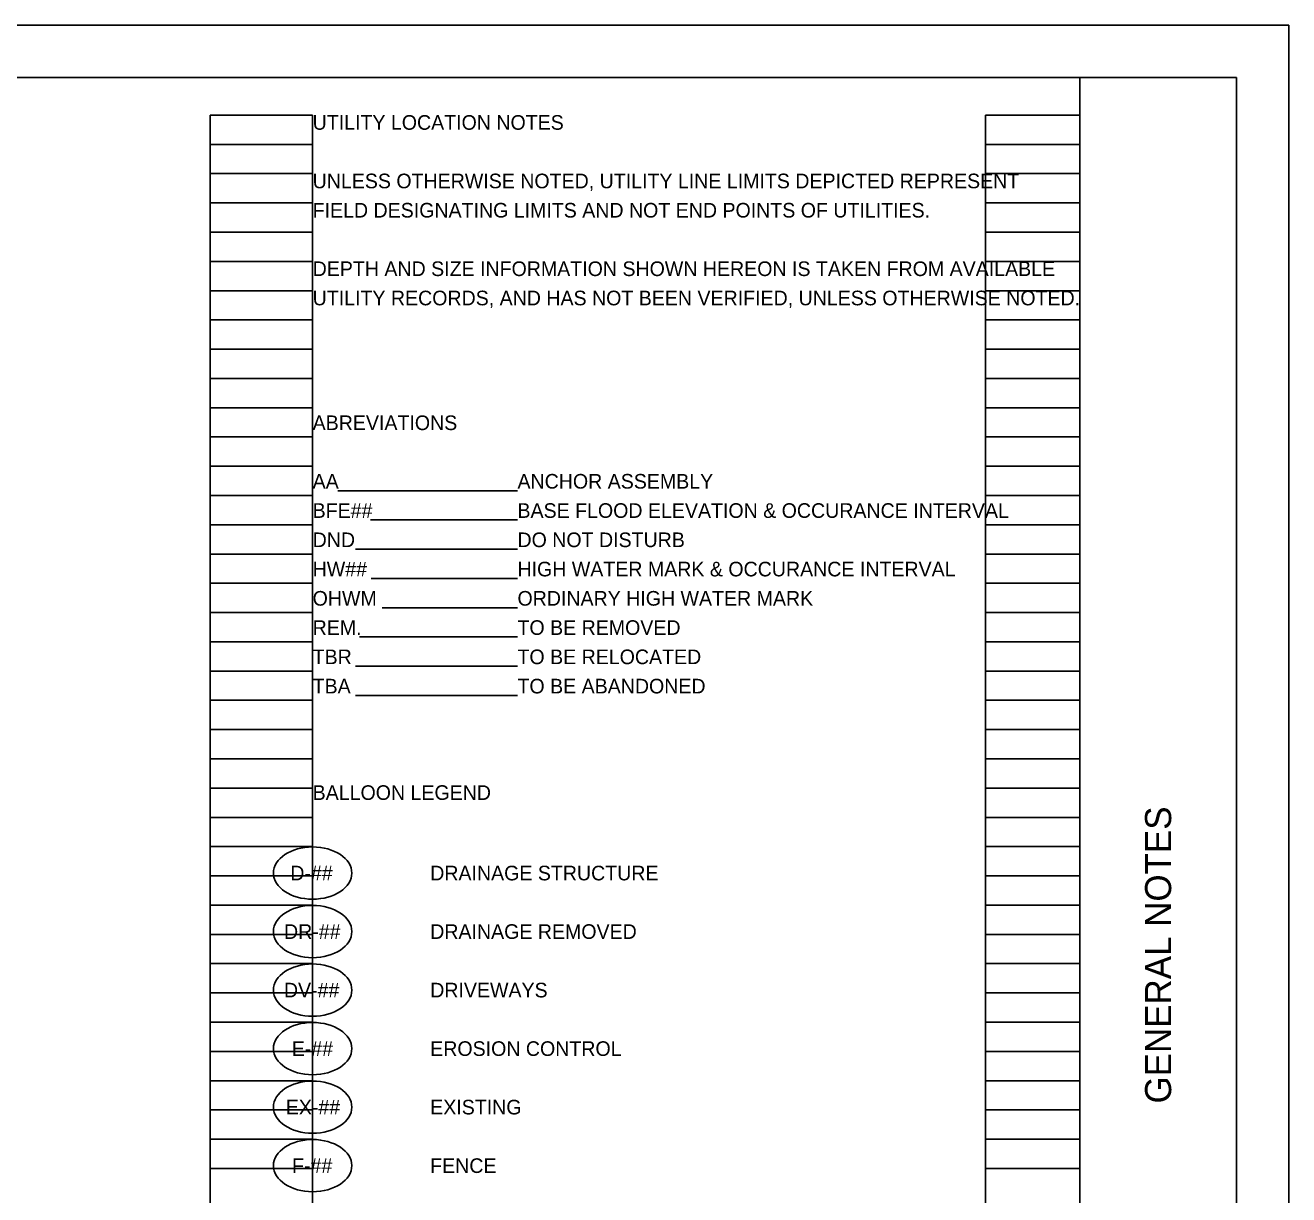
# Model space of a CAD drawing. Extents: x -8.3 to 34, y 0 to 22.
# Drawn here: x 21.91 to 34, y 10.81 to 22 of the extents above; entities that cross this region are included whole.
import ezdxf

# ---------------------------------------------------------------- set-up
doc = ezdxf.new("R2010")
doc.units = 0
for name, color, linetype in [('SH_Border', 7, 'Continuous'), ('SH_Cut_Line', 7, 'Continuous'), ('SH_Data', 7, 'Continuous'), ('SH_Text', 7, 'Continuous')]:
    doc.layers.add(name, color=color, linetype=linetype)

msp = doc.modelspace()

# ---------------------------------------------------------------- linework, layer by layer
at = {"layer": 'SH_Border'}
msp.add_line((32, 0.5), (32, 21.5), dxfattribs=at)
msp.add_lwpolyline([(1.5, 21.5), (33.5, 21.5), (33.5, 0.5), (1.5, 0.5)], close=True, dxfattribs=at)
at = {"layer": 'SH_Cut_Line'}
msp.add_lwpolyline([(0, 0), (34, 0), (34, 22), (0, 22)], close=True, dxfattribs=at)
at = {"layer": 'SH_Data'}
for p, q in [((23.68, 0.98), (23.68, 21.14)), ((23.68, 21.14), (24.66, 21.14)), ((24.66, 0.98), (24.66, 21.14)), ((31.1, 0.98), (31.1, 21.14)), ((31.1, 21.14), (32, 21.14)), ((32, 0.98), (32, 21.14)), ((23.68, 20.86), (24.66, 20.86)), ((31.1, 20.86), (32, 20.86)), ((23.68, 20.58), (24.66, 20.58)), ((31.1, 20.58), (32, 20.58)), ((23.68, 20.3), (24.66, 20.3)), ((31.1, 20.3), (32, 20.3)), ((23.68, 20.02), (24.66, 20.02)), ((31.1, 20.02), (32, 20.02)), ((23.68, 19.74), (24.66, 19.74)), ((31.1, 19.74), (32, 19.74)), ((23.68, 19.46), (24.66, 19.46)), ((31.1, 19.46), (32, 19.46)), ((23.68, 19.18), (24.66, 19.18)), ((31.1, 19.18), (32, 19.18)), ((23.68, 18.9), (24.66, 18.9)), ((31.1, 18.9), (32, 18.9)), ((23.68, 18.62), (24.66, 18.62)), ((31.1, 18.62), (32, 18.62)), ((23.68, 18.34), (24.66, 18.34)), ((31.1, 18.34), (32, 18.34)), ((23.68, 18.06), (24.66, 18.06)), ((31.1, 18.06), (32, 18.06)), ((23.68, 17.78), (24.66, 17.78)), ((31.1, 17.78), (32, 17.78)), ((23.68, 17.5), (24.66, 17.5)), ((31.1, 17.5), (32, 17.5)), ((23.68, 17.22), (24.66, 17.22)), ((31.1, 17.22), (32, 17.22)), ((23.68, 16.94), (24.66, 16.94)), ((31.1, 16.94), (32, 16.94)), ((23.68, 16.66), (24.66, 16.66)), ((31.1, 16.66), (32, 16.66)), ((23.68, 16.38), (24.66, 16.38)), ((31.1, 16.38), (32, 16.38)), ((23.68, 16.1), (24.66, 16.1)), ((31.1, 16.1), (32, 16.1)), ((23.68, 15.82), (24.66, 15.82)), ((31.1, 15.82), (32, 15.82)), ((23.68, 15.54), (24.66, 15.54)), ((31.1, 15.54), (32, 15.54)), ((23.68, 15.26), (24.66, 15.26)), ((31.1, 15.26), (32, 15.26)), ((23.68, 14.98), (24.66, 14.98)), ((31.1, 14.98), (32, 14.98)), ((23.68, 14.7), (24.66, 14.7)), ((31.1, 14.7), (32, 14.7)), ((23.68, 14.42), (24.66, 14.42)), ((31.1, 14.42), (32, 14.42)), ((23.68, 14.14), (24.66, 14.14)), ((31.1, 14.14), (32, 14.14)), ((23.68, 13.86), (24.66, 13.86)), ((31.1, 13.86), (32, 13.86)), ((23.68, 13.58), (24.66, 13.58)), ((31.1, 13.58), (32, 13.58)), ((23.68, 13.3), (24.66, 13.3)), ((31.1, 13.3), (32, 13.3)), ((23.68, 13.02), (24.66, 13.02)), ((31.1, 13.02), (32, 13.02)), ((23.68, 12.74), (24.66, 12.74)), ((31.1, 12.74), (32, 12.74)), ((23.68, 12.46), (24.66, 12.46)), ((31.1, 12.46), (32, 12.46)), ((23.68, 12.18), (24.66, 12.18)), ((31.1, 12.18), (32, 12.18)), ((23.68, 11.9), (24.66, 11.9)), ((31.1, 11.9), (32, 11.9)), ((23.68, 11.62), (24.66, 11.62)), ((31.1, 11.62), (32, 11.62)), ((23.68, 11.34), (24.66, 11.34)), ((31.1, 11.34), (32, 11.34)), ((23.68, 11.06), (24.66, 11.06)), ((31.1, 11.06), (32, 11.06))]:
    msp.add_line(p, q, dxfattribs=at)
at = {"layer": 'SH_Text'}
for p, q in [((24.902, 17.546), (26.62, 17.546)), ((25.214, 17.266), (26.62, 17.266)), ((25.069, 16.986), (26.62, 16.986)), ((25.219, 16.706), (26.62, 16.706)), ((25.325, 16.426), (26.62, 16.426)), ((25.108, 16.146), (26.62, 16.146)), ((25.069, 15.866), (26.62, 15.866)), ((25.069, 15.586), (26.62, 15.586))]:
    msp.add_line(p, q, dxfattribs=at)
for centre in [(24.66, 13.887), (24.66, 13.327), (24.66, 12.767), (24.66, 12.207), (24.66, 11.647), (24.66, 11.087)]:
    msp.add_ellipse(centre, major_axis=(0.375, 0), ratio=0.666667, dxfattribs=at)

# ---------------------------------------------------------------- texts
at = {"layer": 'SH_Data'}
msp.add_text('GENERAL NOTES', height=0.25, rotation=90, dxfattribs=at).set_placement((32.875, 11.682))
at = {"layer": 'SH_Text'}
for s, p in [('UTILITY LOCATION NOTES', (24.66, 21)), ('UNLESS OTHERWISE NOTED, UTILITY LINE LIMITS DEPICTED REPRESENT', (24.66, 20.44)), ('FIELD DESIGNATING LIMITS AND NOT END POINTS OF UTILITIES.', (24.66, 20.16)), ('DEPTH AND SIZE INFORMATION SHOWN HEREON IS TAKEN FROM AVAILABLE', (24.66, 19.6)), ('UTILITY RECORDS, AND HAS NOT BEEN VERIFIED, UNLESS OTHERWISE NOTED.', (24.66, 19.32)), ('ABREVIATIONS', (24.66, 18.126)), ('AA', (24.66, 17.566)), ('ANCHOR ASSEMBLY', (26.62, 17.566)), ('BFE##', (24.66, 17.286)), ('BASE FLOOD ELEVATION & OCCURANCE INTERVAL', (26.62, 17.286)), ('DND', (24.66, 17.006)), ('DO NOT DISTURB', (26.62, 17.006)), ('HW##', (24.66, 16.726)), ('HIGH WATER MARK & OCCURANCE INTERVAL', (26.62, 16.726)), ('OHWM', (24.66, 16.446)), ('ORDINARY HIGH WATER MARK', (26.62, 16.446)), ('REM.', (24.66, 16.166)), ('TO BE REMOVED', (26.62, 16.166)), ('TBR', (24.66, 15.886)), ('TO BE RELOCATED', (26.62, 15.886)), ('TBA', (24.66, 15.606)), ('TO BE ABANDONED', (26.62, 15.606)), ('BALLOON LEGEND', (24.66, 14.587)), ('D-##', (24.446, 13.817)), ('DRAINAGE STRUCTURE', (25.785, 13.817)), ('DR-##', (24.386, 13.257)), ('DRAINAGE REMOVED', (25.785, 13.257)), ('DV-##', (24.385, 12.697)), ('DRIVEWAYS', (25.785, 12.697)), ('E-##', (24.46, 12.137)), ('EROSION CONTROL', (25.785, 12.137)), ('EX-##', (24.403, 11.577)), ('EXISTING', (25.785, 11.577)), ('F-##', (24.463, 11.017)), ('FENCE', (25.785, 11.017))]:
    msp.add_text(s, height=0.14, dxfattribs=at).set_placement(p)

doc.saveas('drawing.dxf')
